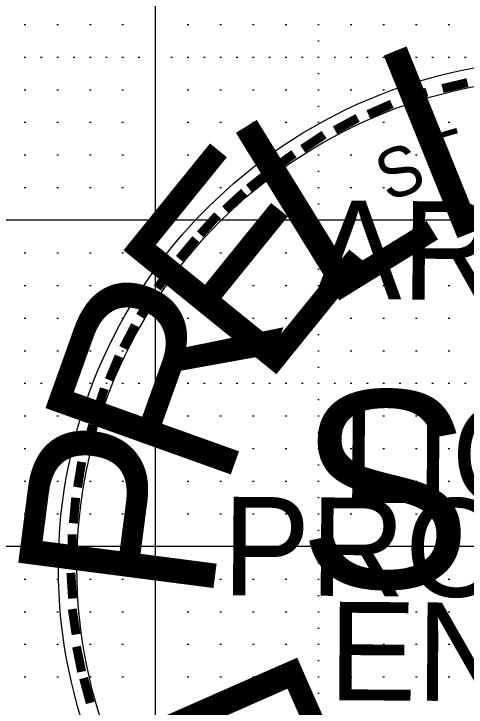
# Model space of a CAD drawing. Extents: x 0 to 34, y 0 to 22.
# Drawn here: x 28.972 to 30.359, y 17.779 to 19.904 of the extents above; entities that cross this region are included whole.
import ezdxf

# ---------------------------------------------------------------- set-up
doc = ezdxf.new("R2010")
doc.units = 0
for name, color, linetype in [('Level 4', 7, 'Continuous'), ('Level 49', 7, 'Continuous'), ('Level 5', 7, 'Continuous'), ('R_Border Prelim', 7, 'Continuous'), ('Stamp Mask', 7, 'Continuous')]:
    doc.layers.add(name, color=color, linetype=linetype)

msp = doc.modelspace()

# ---------------------------------------------------------------- linework, layer by layer
at = {"layer": 'Level 4'}
for p, q in [((29.406, 1.272), (29.406, 20.272)), ((33.215, 19.272), (1.597, 19.272)), ((33.215, 18.272), (1.597, 18.272))]:
    msp.add_line(p, q, dxfattribs=at)
at = {"layer": 'Level 5'}
for p, q in [((29.0035, 19.8719), (29.0085, 19.8719)), ((29.1035, 19.8719), (29.1085, 19.8719)), ((29.2035, 19.8719), (29.2085, 19.8719)), ((29.3035, 19.8719), (29.3085, 19.8719)), ((29.5035, 19.8719), (29.5085, 19.8719)), ((29.6035, 19.8719), (29.6085, 19.8719)), ((29.7035, 19.8719), (29.7085, 19.8719)), ((29.8035, 19.8719), (29.8085, 19.8719)), ((29.9035, 19.8719), (29.9085, 19.8719)), ((30.0035, 19.8719), (30.0085, 19.8719)), ((30.1035, 19.8719), (30.1085, 19.8719)), ((30.2035, 19.8719), (30.2085, 19.8719)), ((30.3035, 19.8719), (30.3085, 19.8719)), ((29.9035, 19.8219), (29.9085, 19.8219)), ((29.0035, 19.7719), (29.0085, 19.7719)), ((29.0535, 19.7719), (29.0585, 19.7719)), ((29.1035, 19.7719), (29.1085, 19.7719)), ((29.1535, 19.7719), (29.1585, 19.7719)), ((29.2035, 19.7719), (29.2085, 19.7719)), ((29.2535, 19.7719), (29.2585, 19.7719)), ((29.3035, 19.7719), (29.3085, 19.7719)), ((29.3535, 19.7719), (29.3585, 19.7719)), ((29.4535, 19.7719), (29.4585, 19.7719)), ((29.5035, 19.7719), (29.5085, 19.7719)), ((29.5535, 19.7719), (29.5585, 19.7719)), ((29.6035, 19.7719), (29.6085, 19.7719)), ((29.6535, 19.7719), (29.6585, 19.7719)), ((29.7035, 19.7719), (29.7085, 19.7719)), ((29.7535, 19.7719), (29.7585, 19.7719)), ((29.8035, 19.7719), (29.8085, 19.7719)), ((29.8535, 19.7719), (29.8585, 19.7719)), ((29.9035, 19.7719), (29.9085, 19.7719)), ((29.9535, 19.7719), (29.9585, 19.7719)), ((30.0035, 19.7719), (30.0085, 19.7719)), ((30.0535, 19.7719), (30.0585, 19.7719)), ((30.1035, 19.7719), (30.1085, 19.7719)), ((30.1535, 19.7719), (30.1585, 19.7719)), ((30.2035, 19.7719), (30.2085, 19.7719)), ((30.2535, 19.7719), (30.2585, 19.7719)), ((30.3035, 19.7719), (30.3085, 19.7719)), ((30.3535, 19.7719), (30.3585, 19.7719)), ((29.9035, 19.7219), (29.9085, 19.7219)), ((29.0035, 19.6719), (29.0085, 19.6719)), ((29.1035, 19.6719), (29.1085, 19.6719)), ((29.2035, 19.6719), (29.2085, 19.6719)), ((29.3035, 19.6719), (29.3085, 19.6719)), ((29.5035, 19.6719), (29.5085, 19.6719)), ((29.6035, 19.6719), (29.6085, 19.6719)), ((29.7035, 19.6719), (29.7085, 19.6719)), ((29.8035, 19.6719), (29.8085, 19.6719)), ((29.9035, 19.6719), (29.9085, 19.6719)), ((30.0035, 19.6719), (30.0085, 19.6719)), ((30.1035, 19.6719), (30.1085, 19.6719)), ((30.2035, 19.6719), (30.2085, 19.6719)), ((30.3035, 19.6719), (30.3085, 19.6719)), ((29.9035, 19.6219), (29.9085, 19.6219)), ((29.0035, 19.5719), (29.0085, 19.5719)), ((29.1035, 19.5719), (29.1085, 19.5719)), ((29.2035, 19.5719), (29.2085, 19.5719)), ((29.3035, 19.5719), (29.3085, 19.5719)), ((29.5035, 19.5719), (29.5085, 19.5719)), ((29.6035, 19.5719), (29.6085, 19.5719)), ((29.7035, 19.5719), (29.7085, 19.5719)), ((29.8035, 19.5719), (29.8085, 19.5719)), ((29.9035, 19.5719), (29.9085, 19.5719)), ((30.0035, 19.5719), (30.0085, 19.5719)), ((30.1035, 19.5719), (30.1085, 19.5719)), ((30.2035, 19.5719), (30.2085, 19.5719)), ((30.3035, 19.5719), (30.3085, 19.5719)), ((29.9035, 19.5219), (29.9085, 19.5219)), ((29.0035, 19.4719), (29.0085, 19.4719)), ((29.1035, 19.4719), (29.1085, 19.4719)), ((29.2035, 19.4719), (29.2085, 19.4719)), ((29.3035, 19.4719), (29.3085, 19.4719)), ((29.5035, 19.4719), (29.5085, 19.4719)), ((29.6035, 19.4719), (29.6085, 19.4719)), ((29.7035, 19.4719), (29.7085, 19.4719)), ((29.8035, 19.4719), (29.8085, 19.4719)), ((29.9035, 19.4719), (29.9085, 19.4719)), ((30.0035, 19.4719), (30.0085, 19.4719)), ((30.1035, 19.4719), (30.1085, 19.4719)), ((30.2035, 19.4719), (30.2085, 19.4719)), ((30.3035, 19.4719), (30.3085, 19.4719)), ((29.9035, 19.4219), (29.9085, 19.4219)), ((29.0035, 19.3719), (29.0085, 19.3719)), ((29.1035, 19.3719), (29.1085, 19.3719)), ((29.2035, 19.3719), (29.2085, 19.3719)), ((29.3035, 19.3719), (29.3085, 19.3719)), ((29.5035, 19.3719), (29.5085, 19.3719)), ((29.6035, 19.3719), (29.6085, 19.3719)), ((29.7035, 19.3719), (29.7085, 19.3719)), ((29.8035, 19.3719), (29.8085, 19.3719)), ((29.9035, 19.3719), (29.9085, 19.3719)), ((30.0035, 19.3719), (30.0085, 19.3719)), ((30.1035, 19.3719), (30.1085, 19.3719)), ((30.2035, 19.3719), (30.2085, 19.3719)), ((30.3035, 19.3719), (30.3085, 19.3719)), ((29.9035, 19.3219), (29.9085, 19.3219)), ((29.9035, 19.2219), (29.9085, 19.2219)), ((29.0035, 19.1719), (29.0085, 19.1719)), ((29.1035, 19.1719), (29.1085, 19.1719)), ((29.2035, 19.1719), (29.2085, 19.1719)), ((29.3035, 19.1719), (29.3085, 19.1719)), ((29.5035, 19.1719), (29.5085, 19.1719)), ((29.6035, 19.1719), (29.6085, 19.1719)), ((29.7035, 19.1719), (29.7085, 19.1719)), ((29.8035, 19.1719), (29.8085, 19.1719)), ((29.9035, 19.1719), (29.9085, 19.1719)), ((30.0035, 19.1719), (30.0085, 19.1719)), ((30.1035, 19.1719), (30.1085, 19.1719)), ((30.2035, 19.1719), (30.2085, 19.1719)), ((30.3035, 19.1719), (30.3085, 19.1719)), ((29.9035, 19.1219), (29.9085, 19.1219)), ((29.0035, 19.0719), (29.0085, 19.0719)), ((29.1035, 19.0719), (29.1085, 19.0719)), ((29.2035, 19.0719), (29.2085, 19.0719)), ((29.3035, 19.0719), (29.3085, 19.0719)), ((29.5035, 19.0719), (29.5085, 19.0719)), ((29.6035, 19.0719), (29.6085, 19.0719)), ((29.7035, 19.0719), (29.7085, 19.0719)), ((29.8035, 19.0719), (29.8085, 19.0719)), ((29.9035, 19.0719), (29.9085, 19.0719)), ((30.0035, 19.0719), (30.0085, 19.0719)), ((30.1035, 19.0719), (30.1085, 19.0719)), ((30.2035, 19.0719), (30.2085, 19.0719)), ((30.3035, 19.0719), (30.3085, 19.0719)), ((29.9035, 19.0219), (29.9085, 19.0219)), ((29.0035, 18.9719), (29.0085, 18.9719)), ((29.1035, 18.9719), (29.1085, 18.9719)), ((29.2035, 18.9719), (29.2085, 18.9719)), ((29.3035, 18.9719), (29.3085, 18.9719)), ((29.5035, 18.9719), (29.5085, 18.9719)), ((29.6035, 18.9719), (29.6085, 18.9719)), ((29.7035, 18.9719), (29.7085, 18.9719)), ((29.8035, 18.9719), (29.8085, 18.9719)), ((29.9035, 18.9719), (29.9085, 18.9719)), ((30.0035, 18.9719), (30.0085, 18.9719)), ((30.1035, 18.9719), (30.1085, 18.9719)), ((30.2035, 18.9719), (30.2085, 18.9719)), ((30.3035, 18.9719), (30.3085, 18.9719)), ((29.9035, 18.9219), (29.9085, 18.9219)), ((29.0035, 18.8719), (29.0085, 18.8719)), ((29.1035, 18.8719), (29.1085, 18.8719)), ((29.2035, 18.8719), (29.2085, 18.8719)), ((29.3035, 18.8719), (29.3085, 18.8719)), ((29.5035, 18.8719), (29.5085, 18.8719)), ((29.6035, 18.8719), (29.6085, 18.8719)), ((29.7035, 18.8719), (29.7085, 18.8719)), ((29.8035, 18.8719), (29.8085, 18.8719)), ((29.9035, 18.8719), (29.9085, 18.8719)), ((30.0035, 18.8719), (30.0085, 18.8719)), ((30.1035, 18.8719), (30.1085, 18.8719)), ((30.2035, 18.8719), (30.2085, 18.8719)), ((30.3035, 18.8719), (30.3085, 18.8719)), ((29.9035, 18.8219), (29.9085, 18.8219)), ((29.0035, 18.7719), (29.0085, 18.7719)), ((29.0535, 18.7719), (29.0585, 18.7719)), ((29.1035, 18.7719), (29.1085, 18.7719)), ((29.1535, 18.7719), (29.1585, 18.7719)), ((29.2035, 18.7719), (29.2085, 18.7719)), ((29.2535, 18.7719), (29.2585, 18.7719)), ((29.3035, 18.7719), (29.3085, 18.7719)), ((29.3535, 18.7719), (29.3585, 18.7719)), ((29.4535, 18.7719), (29.4585, 18.7719)), ((29.5035, 18.7719), (29.5085, 18.7719)), ((29.5535, 18.7719), (29.5585, 18.7719)), ((29.6035, 18.7719), (29.6085, 18.7719)), ((29.6535, 18.7719), (29.6585, 18.7719)), ((29.7035, 18.7719), (29.7085, 18.7719)), ((29.7535, 18.7719), (29.7585, 18.7719)), ((29.8035, 18.7719), (29.8085, 18.7719)), ((29.8535, 18.7719), (29.8585, 18.7719)), ((29.9035, 18.7719), (29.9085, 18.7719)), ((29.9535, 18.7719), (29.9585, 18.7719)), ((30.0035, 18.7719), (30.0085, 18.7719)), ((30.0535, 18.7719), (30.0585, 18.7719)), ((30.1035, 18.7719), (30.1085, 18.7719)), ((30.1535, 18.7719), (30.1585, 18.7719)), ((30.2035, 18.7719), (30.2085, 18.7719)), ((30.2535, 18.7719), (30.2585, 18.7719)), ((30.3035, 18.7719), (30.3085, 18.7719)), ((30.3535, 18.7719), (30.3585, 18.7719)), ((29.9035, 18.7219), (29.9085, 18.7219)), ((29.0035, 18.6719), (29.0085, 18.6719)), ((29.1035, 18.6719), (29.1085, 18.6719)), ((29.2035, 18.6719), (29.2085, 18.6719)), ((29.3035, 18.6719), (29.3085, 18.6719)), ((29.5035, 18.6719), (29.5085, 18.6719)), ((29.6035, 18.6719), (29.6085, 18.6719)), ((29.7035, 18.6719), (29.7085, 18.6719)), ((29.8035, 18.6719), (29.8085, 18.6719)), ((29.9035, 18.6719), (29.9085, 18.6719)), ((30.0035, 18.6719), (30.0085, 18.6719)), ((30.1035, 18.6719), (30.1085, 18.6719)), ((30.2035, 18.6719), (30.2085, 18.6719)), ((30.3035, 18.6719), (30.3085, 18.6719)), ((29.9035, 18.6219), (29.9085, 18.6219)), ((29.0035, 18.5719), (29.0085, 18.5719)), ((29.1035, 18.5719), (29.1085, 18.5719)), ((29.2035, 18.5719), (29.2085, 18.5719)), ((29.3035, 18.5719), (29.3085, 18.5719)), ((29.5035, 18.5719), (29.5085, 18.5719)), ((29.6035, 18.5719), (29.6085, 18.5719)), ((29.7035, 18.5719), (29.7085, 18.5719)), ((29.8035, 18.5719), (29.8085, 18.5719)), ((29.9035, 18.5719), (29.9085, 18.5719)), ((30.0035, 18.5719), (30.0085, 18.5719)), ((30.1035, 18.5719), (30.1085, 18.5719)), ((30.2035, 18.5719), (30.2085, 18.5719)), ((30.3035, 18.5719), (30.3085, 18.5719)), ((29.9035, 18.5219), (29.9085, 18.5219)), ((29.0035, 18.4719), (29.0085, 18.4719)), ((29.1035, 18.4719), (29.1085, 18.4719)), ((29.2035, 18.4719), (29.2085, 18.4719)), ((29.3035, 18.4719), (29.3085, 18.4719)), ((29.5035, 18.4719), (29.5085, 18.4719)), ((29.6035, 18.4719), (29.6085, 18.4719)), ((29.7035, 18.4719), (29.7085, 18.4719)), ((29.8035, 18.4719), (29.8085, 18.4719)), ((29.9035, 18.4719), (29.9085, 18.4719)), ((30.0035, 18.4719), (30.0085, 18.4719)), ((30.1035, 18.4719), (30.1085, 18.4719)), ((30.2035, 18.4719), (30.2085, 18.4719)), ((30.3035, 18.4719), (30.3085, 18.4719)), ((29.9035, 18.4219), (29.9085, 18.4219)), ((29.0035, 18.3719), (29.0085, 18.3719)), ((29.1035, 18.3719), (29.1085, 18.3719)), ((29.2035, 18.3719), (29.2085, 18.3719)), ((29.3035, 18.3719), (29.3085, 18.3719)), ((29.5035, 18.3719), (29.5085, 18.3719)), ((29.6035, 18.3719), (29.6085, 18.3719)), ((29.7035, 18.3719), (29.7085, 18.3719)), ((29.8035, 18.3719), (29.8085, 18.3719)), ((29.9035, 18.3719), (29.9085, 18.3719)), ((30.0035, 18.3719), (30.0085, 18.3719)), ((30.1035, 18.3719), (30.1085, 18.3719)), ((30.2035, 18.3719), (30.2085, 18.3719)), ((30.3035, 18.3719), (30.3085, 18.3719)), ((29.9035, 18.3219), (29.9085, 18.3219)), ((29.9035, 18.2219), (29.9085, 18.2219)), ((29.0035, 18.1719), (29.0085, 18.1719)), ((29.1035, 18.1719), (29.1085, 18.1719)), ((29.2035, 18.1719), (29.2085, 18.1719)), ((29.3035, 18.1719), (29.3085, 18.1719)), ((29.5035, 18.1719), (29.5085, 18.1719)), ((29.6035, 18.1719), (29.6085, 18.1719)), ((29.7035, 18.1719), (29.7085, 18.1719)), ((29.8035, 18.1719), (29.8085, 18.1719)), ((29.9035, 18.1719), (29.9085, 18.1719)), ((30.0035, 18.1719), (30.0085, 18.1719)), ((30.1035, 18.1719), (30.1085, 18.1719)), ((30.2035, 18.1719), (30.2085, 18.1719)), ((30.3035, 18.1719), (30.3085, 18.1719)), ((29.9035, 18.1219), (29.9085, 18.1219)), ((29.0035, 18.0719), (29.0085, 18.0719)), ((29.1035, 18.0719), (29.1085, 18.0719)), ((29.2035, 18.0719), (29.2085, 18.0719)), ((29.3035, 18.0719), (29.3085, 18.0719)), ((29.5035, 18.0719), (29.5085, 18.0719)), ((29.6035, 18.0719), (29.6085, 18.0719)), ((29.7035, 18.0719), (29.7085, 18.0719)), ((29.8035, 18.0719), (29.8085, 18.0719)), ((29.9035, 18.0719), (29.9085, 18.0719)), ((30.0035, 18.0719), (30.0085, 18.0719)), ((30.1035, 18.0719), (30.1085, 18.0719)), ((30.2035, 18.0719), (30.2085, 18.0719)), ((30.3035, 18.0719), (30.3085, 18.0719)), ((29.9035, 18.0219), (29.9085, 18.0219)), ((29.0035, 17.9719), (29.0085, 17.9719)), ((29.1035, 17.9719), (29.1085, 17.9719)), ((29.2035, 17.9719), (29.2085, 17.9719)), ((29.3035, 17.9719), (29.3085, 17.9719)), ((29.5035, 17.9719), (29.5085, 17.9719)), ((29.6035, 17.9719), (29.6085, 17.9719)), ((29.7035, 17.9719), (29.7085, 17.9719)), ((29.8035, 17.9719), (29.8085, 17.9719)), ((29.9035, 17.9719), (29.9085, 17.9719)), ((30.0035, 17.9719), (30.0085, 17.9719)), ((30.1035, 17.9719), (30.1085, 17.9719)), ((30.2035, 17.9719), (30.2085, 17.9719)), ((30.3035, 17.9719), (30.3085, 17.9719)), ((29.9035, 17.9219), (29.9085, 17.9219)), ((29.0035, 17.8719), (29.0085, 17.8719)), ((29.1035, 17.8719), (29.1085, 17.8719)), ((29.2035, 17.8719), (29.2085, 17.8719)), ((29.3035, 17.8719), (29.3085, 17.8719)), ((29.5035, 17.8719), (29.5085, 17.8719)), ((29.6035, 17.8719), (29.6085, 17.8719)), ((29.7035, 17.8719), (29.7085, 17.8719)), ((29.8035, 17.8719), (29.8085, 17.8719)), ((29.9035, 17.8719), (29.9085, 17.8719)), ((30.0035, 17.8719), (30.0085, 17.8719)), ((30.1035, 17.8719), (30.1085, 17.8719)), ((30.2035, 17.8719), (30.2085, 17.8719)), ((30.3035, 17.8719), (30.3085, 17.8719)), ((29.9035, 17.8219), (29.9085, 17.8219))]:
    msp.add_line(p, q, dxfattribs=at)
at = {"layer": 'R_Border Prelim'}
msp.add_circle((30.6652, 18.2078), 1.5001, dxfattribs=at)
at = {"layer": 'Stamp Mask'}
msp.add_circle((30.6652, 18.2078), 1.5568, dxfattribs=at)

# ---------------------------------------------------------------- texts
at = {"layer": 'Level 49'}
for s, height, rotation, p in [('-', 0.2412, 13.2326, (30.2935, 19.5817)), ('-', 0.2412, 18.7785, (30.18, 19.5464)), ('-', 0.2412, 23.9096, (30.0833, 19.5054)), ('-', 0.2412, 28.3942, (29.9884, 19.4589)), ('T', 0.1507, 16.006, (30.2563, 19.377)), ('-', 0.2412, 33.666, (29.8972, 19.405)), ('-', 0.2412, 35.8341, (29.8097, 19.3454)), ('S', 0.1507, 21.1964, (30.1186, 19.3268)), ('-', 0.2412, 38.5531, (29.739, 19.2877)), ('-', 0.2412, 42.5646, (29.672, 19.2263)), ('ARKANSAS', 0.30153, 359.6024, (29.8916, 19.0309)), ('-', 0.2412, 48.0254, (29.6032, 19.1556)), ('-', 0.2412, 50.2166, (29.5417, 19.083)), ('-', 0.2412, 53.8349, (29.4785, 18.9974)), ('-', 0.2412, 57.673, (29.4301, 18.9155)), ('-', 0.2412, 62.4738, (29.3836, 18.8244)), ('-', 0.2412, 67.3767, (29.3445, 18.7332)), ('-', 0.2412, 71.9969, (29.3091, 18.6383)), ('LICENSED', 0.30153, 359.6024, (29.9759, 18.4062)), ('-', 0.2412, 75.0634, (29.2794, 18.5303)), ('-', 0.2412, 80.8037, (29.257, 18.4243)), ('PROFESSIONAL', 0.301532, 359.6024, (29.6106, 18.1228)), ('-', 0.2412, 84.7887, (29.2459, 18.3201)), ('-', 0.2412, 88.6646, (29.2421, 18.214)), ('-', 0.2412, 93.7983, (29.2459, 18.1042)), ('ENGINEER', 0.30153, 359.6024, (29.9363, 17.8009)), ('-', 0.2412, 98.5503, (29.257, 18.0018)), ('-', 0.2412, 101.3173, (29.2738, 17.892)), ('-', 0.2412, 105.0602, (29.2998, 17.8027))]:
    msp.add_text(s, height=height, rotation=rotation, dxfattribs=at).set_placement(p)
at = {"layer": 'R_Border Prelim'}
for s, rotation, p in [('I', 22.0105, (30.2632, 19.189)), ('L', 31.6686, (29.9132, 18.9914)), ('E', 50.9849, (29.7352, 18.7485)), ('R', 70.3011, (29.6146, 18.4303)), ('P', 82.6089, (29.5754, 18.0788)), ('R', 293.7639, (29.2616, 17.7485))]:
    msp.add_text(s, height=0.6034, rotation=rotation, dxfattribs=at).set_placement(p)
msp.add_text('SUBJECT', height=0.60336, dxfattribs=at).set_placement((29.8408, 18.1452))

doc.saveas('drawing.dxf')
